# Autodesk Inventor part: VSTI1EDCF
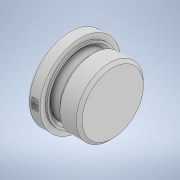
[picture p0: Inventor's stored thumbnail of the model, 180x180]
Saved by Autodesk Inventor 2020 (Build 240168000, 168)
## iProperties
Created: 2019-12
Part Number: VSTI1EDCF
Material: Generico
Description: STEP AP203
Document SubType Name: Modeling
Designer: carlo
Density: 1 g/cm^3
Appearance: Default
DataBaseUnit: MM
Title: p:/temp/worker_142/temp/exporttempdir_4540_375_0gz38/format_0/EO Verschluss-Stopfen fuer Einschraubloecher VSTI1EDCF.stp
Revision Number: NONE
Sending System: PARTsolutions
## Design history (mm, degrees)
feature "_EO Verschluss-Stopfen fuer Einschraubloecher VSTI1EDCF"
node "Piano di lavoro1"
node "Piano di lavoro2"
node "Asse di lavoro1"
node "Solido1"
other parameters: "d0" = 0, "d1" = 0
